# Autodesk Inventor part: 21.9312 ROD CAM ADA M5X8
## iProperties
Created: 2007-03
Part Number: 21.9312 ROD CAM ADA M5X8
Document SubType Name: Modeling
Designer: Andy Moles
Material: Steel
Density: 7.85 g/cm^3
Mass: 2.68791 g
Surface Area: 3.21209 cm^2
Volume: 0.342409 cm^3
Author: Andy Moles
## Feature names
1. Base1
